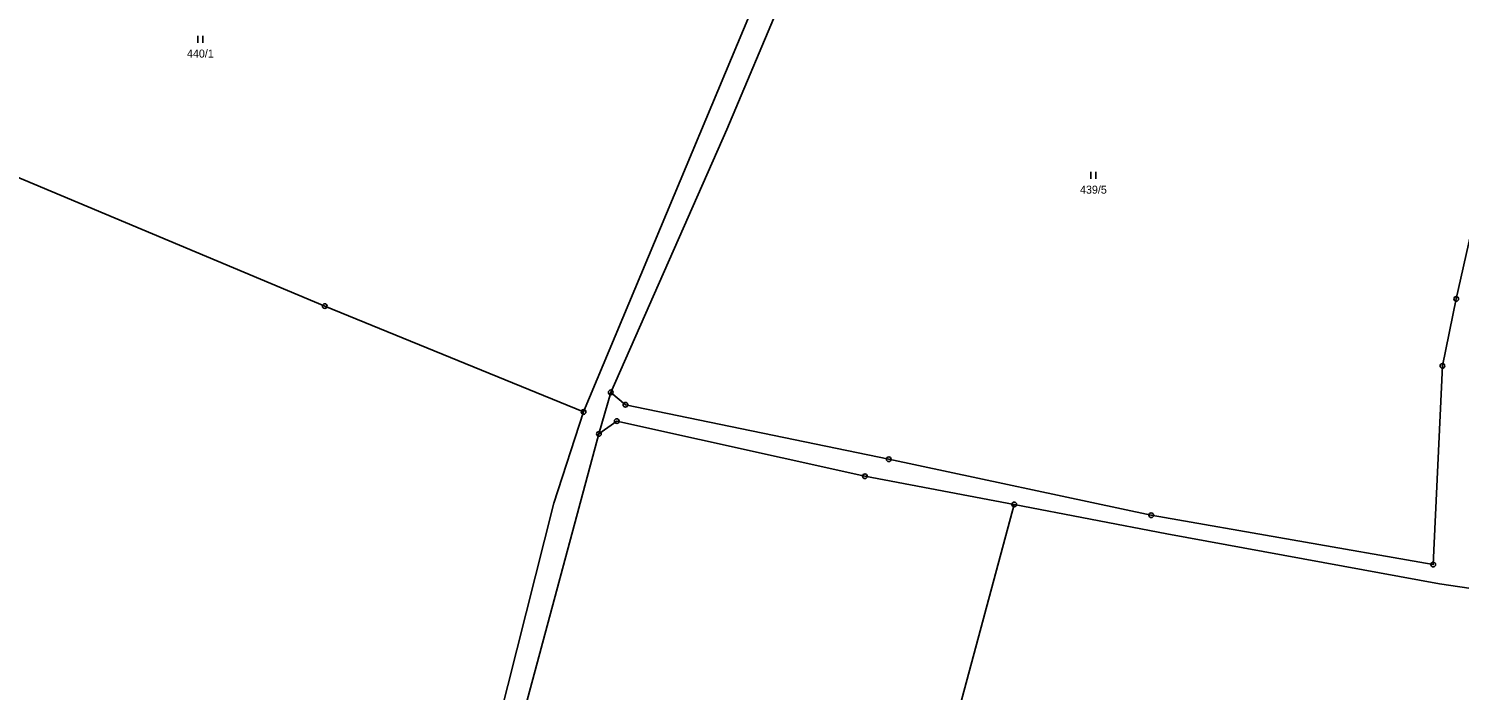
# Model space of a CAD drawing. Extents: x -739410 to -735662, y -942282 to -940043.
# Drawn here: x -737454.1 to -737150.2, y -941193.9 to -941053.4 of the extents above; entities that cross this region are included whole.
import ezdxf
from ezdxf.enums import TextEntityAlignment as Align

# ---------------------------------------------------------------- set-up
doc = ezdxf.new("R2010")
doc.units = 0
doc.header["$LTSCALE"] = 0.68
for name, color, linetype, lineweight in [('1', 7, 'Continuous', 25), ('3', 7, 'Continuous', 25), ('8', 7, 'Continuous', 25)]:
    doc.layers.add(name, color=color, linetype=linetype, lineweight=lineweight)
doc.layers.add('2', color=7, linetype='Continuous')

msp = doc.modelspace()

# ---------------------------------------------------------------- linework, layer by layer
at = {"layer": '1'}
for p, q in [((-737292.38, -941029.92), (-737336.23, -941134.82)), ((-737293.98, -941046.71), (-737305.77, -941074.85)), ((-737511.93, -941061.71), (-737391.18, -941112.33)), ((-737330.44, -941130.65), (-737305.77, -941074.85)), ((-737150.89, -941110.81), (-737145.16, -941085.34)), ((-737391.18, -941112.33), (-737336.23, -941134.82)), ((-737153.82, -941125.04), (-737150.89, -941110.81)), ((-737155.76, -941167.22), (-737153.82, -941125.04)), ((-737330.44, -941130.65), (-737332.96, -941139.48)), ((-737327.34, -941133.29), (-737330.44, -941130.65)), ((-737271.39, -941144.87), (-737327.34, -941133.29)), ((-737336.23, -941134.82), (-737342.51, -941154.16)), ((-737332.96, -941139.48), (-737329.16, -941136.76)), ((-737329.16, -941136.76), (-737276.46, -941148.47)), ((-737332.96, -941139.48), (-737354.17, -941218.16)), ((-737215.67, -941156.74), (-737271.39, -941144.87)), ((-737276.46, -941148.47), (-737244.75, -941154.46)), ((-737342.51, -941154.16), (-737356.53, -941209.52)), ((-737287.08, -941311.26), (-737244.75, -941154.46)), ((-737244.75, -941154.46), (-737212.36, -941160.72)), ((-737155.76, -941167.22), (-737215.67, -941156.74)), ((-737212.36, -941160.72), (-737154.4, -941171.33)), ((-737154.4, -941171.33), (-737094.77, -941180.16))]:
    msp.add_line(p, q, dxfattribs=at)
at = {"layer": '3'}
for p, q in [((-737418.121, -941056.42), (-737418.121, -941054.92)), ((-737417.12, -941056.42), (-737417.12, -941054.92)), ((-737228.451, -941085.32), (-737228.451, -941083.82)), ((-737227.45, -941085.32), (-737227.45, -941083.82))]:
    msp.add_line(p, q, dxfattribs=at)
at = {"layer": '8'}
for centre, radius in [((-737391.18, -941112.3299), 0.5), ((-737391.18, -941112.3299), 0.0303), ((-737150.89, -941110.8099), 0.5), ((-737150.89, -941110.8099), 0.0303), ((-737153.82, -941125.0399), 0.5), ((-737153.82, -941125.0399), 0.0303), ((-737330.44, -941130.6499), 0.5), ((-737330.44, -941130.6499), 0.0303), ((-737336.23, -941134.8199), 0.5), ((-737327.34, -941133.2899), 0.5), ((-737327.34, -941133.2899), 0.0303), ((-737336.23, -941134.8199), 0.0303), ((-737329.16, -941136.7599), 0.5), ((-737329.16, -941136.7599), 0.0303), ((-737332.96, -941139.4799), 0.5), ((-737332.96, -941139.4799), 0.0303), ((-737271.39, -941144.8699), 0.5), ((-737271.39, -941144.8699), 0.0303), ((-737276.46, -941148.4699), 0.5), ((-737276.46, -941148.4699), 0.0303), ((-737244.75, -941154.4599), 0.5), ((-737244.75, -941154.4599), 0.0303), ((-737215.67, -941156.7399), 0.5), ((-737215.67, -941156.7399), 0.0303), ((-737155.76, -941167.2199), 0.5), ((-737155.76, -941167.2199), 0.0303)]:
    msp.add_circle(centre, radius, dxfattribs=at)

# ---------------------------------------------------------------- texts
at = {"layer": '2'}
for s, p in [('440/1', (-737417.61, -941059.545)), ('439/5', (-737227.94, -941088.445))]:
    msp.add_text(s, height=1.7, dxfattribs=at).set_placement(p, align=Align.CENTER)

doc.saveas('drawing.dxf')
